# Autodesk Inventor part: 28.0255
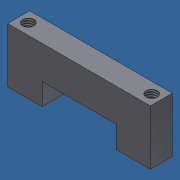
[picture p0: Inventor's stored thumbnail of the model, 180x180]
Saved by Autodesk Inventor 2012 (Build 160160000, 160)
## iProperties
Created: 2012-11
Part Number: 28.0255
Document SubType Name: Modeling
Designer: Administrator
Density: 7.85 g/cm^3
Material: Steel
Mass: 48.499 g
Surface Area: 33.2209 cm^2
Volume: 6.17821 cm^3
Description: NUT SLIDE CONNECTOR 20
Vendor: S
Translation Standard: STEP AP214IS
FileName: K:\Alle\Neum\von Trenz\28.0255 Nut slide connector 20.stp
PreProcessor: Autodesk Inventor 2011
PostProcessor: Build: 236a, Release: 2009 RTM - Date: Fri 02/22/2008
Sent Units: MM
Uncertainty: 0.01
Author: Administrator
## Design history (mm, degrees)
feature "Base1"
sketch "Sketch1"
  geometry: C1 r 2.067 at (48.5, 4) reference; C2 r 2.067 at (3.5, 4) reference; C3 r 2 at (48.5, 4); C4 r 2 at (3.5, 4); 1 further point
  constraints: 2 centre point, 2 coincident
  dimensions: "d0" = 4 diameter of C4; "d1" = 4 diameter of C3
extrude "Extrusion1" join sketch "Sketch1" distance "d2" = 16; taper "d3" = 0 deg
sketch "Sketch2"
  geometry: C1 r 2 at (3.5, 4) reference; C2 r 2 at (48.5, 4) reference; 3 further points
  constraints: 2 coincident
hole "Hole1" sketch "Sketch2" at (3.5, 4), (48.5, 4) diameter "d8" = 4.134; stored, may be unused: countersink angle "d12" = 90 deg, drill point angle "d14" = 118 deg; dims "d9" = 6, "d10" = 4, "d11" = 2, "d13" = 15
body "Solid1"
